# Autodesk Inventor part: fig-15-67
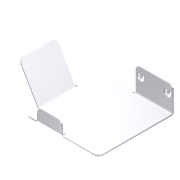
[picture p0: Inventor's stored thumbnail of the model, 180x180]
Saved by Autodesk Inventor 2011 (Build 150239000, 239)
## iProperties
Shininess: 77.0
Angle Display Precision: 2
Document Length Units: 11269
Document Angle Units: 11279
Document Time Units: 11290
Document Mass Units: 11283
Document Length Units Precision: 3
Document Angle Units Precision: 2
Created: 2002-04
Part Number: fig-15-67
Document SubType Name: Sheet Metal
Density: 1 g/cm^3
Sheet Metal Rule: Default
Density: 0.0
Volumn: 0.0
Area: 0.0
PropertySet Name: Model Information
Control State: 0
Master: False
Checked Out: False
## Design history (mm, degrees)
node "Face1"
  sketch "Sketch1"
    geometry: L1 (12.647, 25.882)-(12.647, -14.118); L2 (12.647, -14.118)-(-17.353, -14.118); L3 (-17.353, -14.118)-(-17.353, 15.882); L4 (-17.353, 15.882)-(-2.353, 15.882); L5 (-2.353, 15.882)-(-2.353, 25.882); L6 (-2.353, 25.882)-(12.647, 25.882); 1 further point
    constraints: 12 end point, 4 parallel, 1 perpendicular
    dimensions: "d5" = 30 distance of L2.end L3.end; "d6" = 10 distance of L4.end L5.end; "d7" = 15 distance of L3.end L4.end; "d25" = 15 distance of L5.end L1.start
sketch "Sketch3"
  geometry: L1 (10, -15)-(10, 0)
  constraints: 2 end point
feature "Fold3" sketch "Sketch3" dims "d26" = 0.5 (= BendRadius), "d27" = 90 deg, "d28" = 0.5 (= BendRadius), "d96" = 0.5 (= BendReliefWidth), "d97" = 0.25 (= BendReliefDepth), "d98" = 1 (= MinimumRemnant), "SeamGap" = 0.01, "Thickness" = 0.5
node "Flange2"
sketch "Sketch6"
  geometry: L1 (-6.914, 3.413)-(-5.843, 3.413); L2 (-5.843, 0.624)-(-6.914, 0.624); L3 (-6.914, 2.432)-(-5.843, 2.432); L4 (-5.843, 1.605)-(-6.914, 1.605); L5 (-6.914, 0.624)-(-6.914, 1.605); L6 (-6.914, 2.432)-(-6.914, 3.413); L7 (-6.914, 12.568)-(-6.914, 11.587); L8 (-6.914, 14.376)-(-6.914, 13.395); L9 (-6.914, 11.587)-(-5.843, 11.587); L10 (-5.843, 14.376)-(-6.914, 14.376); L11 (-6.914, 12.568)-(-5.843, 12.568); L12 (-5.843, 13.395)-(-6.914, 13.395); A1 r 1.394 centre (-5.843, 2.018) between (-5.843, 0.624) and (-5.843, 3.413); A2 r 0.413 centre (-5.843, 2.018) between (-5.843, 1.605) and (-5.843, 2.432); A3 r 1.394 centre (-5.843, 12.982) between (-5.843, 11.587) and (-5.843, 14.376); A4 r 0.413 centre (-5.843, 12.982) between (-5.843, 12.568) and (-5.843, 13.395)
  constraints: 24 end point, 8 point on circle, 4 centre point, 3 equal length, 1 perpendicular
cut "Cut1" sketch "Sketch6" dims "d49" = 0.5 (= Thickness), "d50" = 0
node "Flange3"
feature "Corner Round2" dims "d107" = 2
body "Solid1"
face "Plate1" dims "Thickness" = 0.5
sketch "Sketch5"
  geometry: L1 (20, 0)-(5, 0); L2 (5, 0)-(5, 15); L3 (5, 15)-(20, 15); L4 (20, 15)-(20, 0)
  constraints: 8 end point
face "Plate6" dims "d35" = 10, "d36" = 5, "d38" = 15, "d39" = 60 deg, "d40" = 0.5 (= BendRadius), "Thickness" = 0.5, "MinimumRemnant" = 1 (= 2 x Thickness), "BendReliefWidth" = 0.5 (= Thickness)
bend "Bend5" dims "d38" = 15, "d39" = 60 deg, "d40" = 0.5 (= BendRadius), "d99" = 0.5 (= BendReliefWidth), "d100" = 0.25 (= BendReliefDepth), "d101" = 1 (= MinimumRemnant), "SeamGap" = 0.01, "Thickness" = 0.5, "MinimumRemnant" = 1 (= 2 x Thickness), "BendReliefWidth" = 0.5 (= Thickness), "TransitionRadius" = 0.5 (= BendRadius)
sketch "Sketch7"
  geometry: L1 (25, 0)-(15, 0); L2 (15, 0)-(15, 5); L3 (15, 5)-(25, 5); L4 (25, 5)-(25, 0)
  constraints: 8 end point
face "Plate7" dims "d57" = 5, "d58" = 10, "d60" = 5, "d61" = 90 deg, "d62" = 0.5 (= BendRadius), "Thickness" = 0.5, "MinimumRemnant" = 1 (= 2 x Thickness), "BendReliefWidth" = 0.5 (= Thickness)
bend "Bend7" dims "d59" = 0.5 (= BendRadius), "d60" = 5, "d61" = 90 deg, "d62" = 0.5 (= BendRadius), "d102" = 0.5 (= BendReliefWidth), "d103" = 0.25 (= BendReliefDepth), "d104" = 1 (= MinimumRemnant), "SeamGap" = 0.01, "Thickness" = 0.5, "MinimumRemnant" = 1 (= 2 x Thickness), "BendReliefWidth" = 0.5 (= Thickness)
other parameters: "BendRadius" = 0.5 (= Thickness), "BendReliefDepth" = 0.25 (= 0.5 x Thickness), "CornerReliefSize" = 2 (= 4 x Thickness), "d0" = 0.5 (= BendRadius), "d13" = 0.5 (= BendRadius), "d31" = 0.5 (= BendRadius), "d37" = 0.5 (= BendRadius), "JacobiRadiusSize" = 0.5 (= Thickness), "GapSize" = 0.5 (= Thickness)
